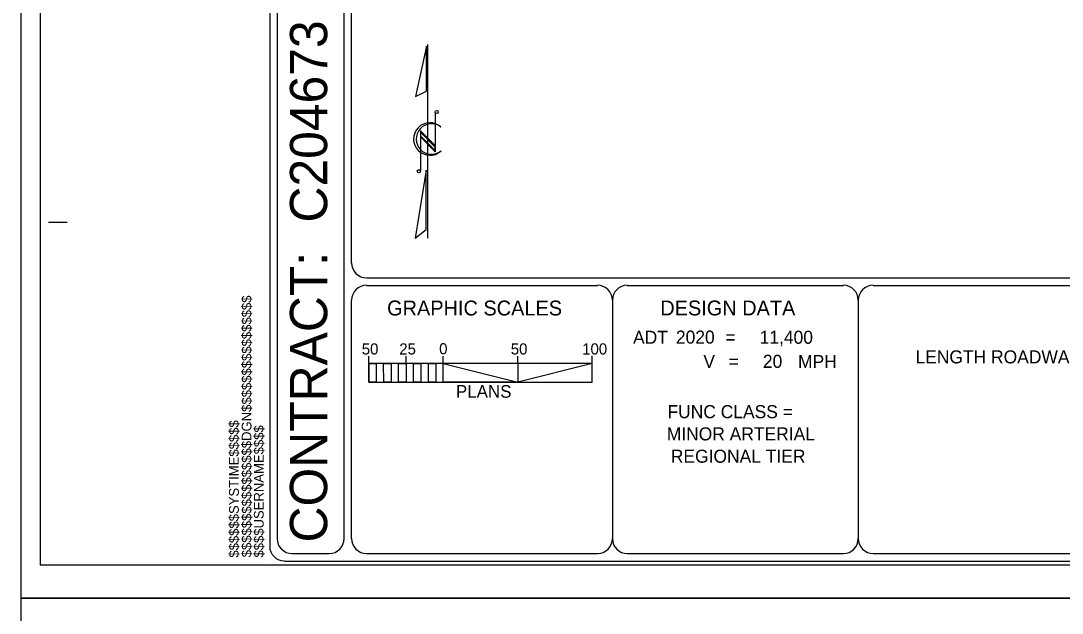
# Model space of a CAD drawing. Extents: x 925297 to 940193, y 663541 to 689899.
# Drawn here: x 925297 to 930888, y 681019 to 684199 of the extents above; entities that cross this region are included whole.
import ezdxf

# ---------------------------------------------------------------- set-up
doc = ezdxf.new("R2010")
doc.units = 0
for name, color, linetype in [('Sheet Cutting Line CELL', 7, 'Continuous'), ('Sheet Data Field CELL', 7, 'Continuous'), ('Sheet North Arrow CELL', 7, 'Continuous'), ('Sheet Plot Border Inside CELL', 7, 'Continuous'), ('Sheet Plot Border Outside CELL', 7, 'Continuous'), ('Sheet Title CELL', 7, 'Continuous')]:
    doc.layers.add(name, color=color, linetype=linetype)

msp = doc.modelspace()

# ---------------------------------------------------------------- linework, layer by layer
at = {"layer": 'Sheet Cutting Line CELL'}
for p, q in [((925296.7, 689898.6), (925296.7, 681098.7)), ((925296.7, 681098.7), (938768.7, 681098.7))]:
    msp.add_line(p, q, dxfattribs=at)
at = {"layer": 'Sheet Data Field CELL'}
for p, q in [((927164.8, 682359.6), (927164.8, 682399.5)), ((927364.8, 682359.5), (927364.8, 682399.5)), ((927964.8, 682359.6), (927964.8, 682399.5)), ((928364.8, 682359.5), (928364.8, 682399.6)), ((926632.8, 681298.7), (926632.8, 681298.7))]:
    msp.add_line(p, q, dxfattribs=at)
at = {"layer": 'Sheet North Arrow CELL'}
for p, q in [((927482.1, 683031.5), (927482.1, 684071.5)), ((927521.3, 683709.6), (927521.3, 683496.1)), ((927521.3, 683529.4), (927441.7, 683608.9)), ((927441.7, 683608.9), (927441.7, 683392)), ((927521.3, 683521.6), (927441.7, 683601.1)), ((927441.7, 683601.1), (927441.7, 683581.6)), ((927550.7, 683630.1), (927551.8, 683629.3)), ((927521.3, 683502.1), (927441.7, 683581.6)), ((927441.7, 683581.6), (927521.3, 683502.1)), ((927521.3, 683496.1), (927441.7, 683575.7)), ((927521.3, 683502.1), (927521.3, 683521.6))]:
    msp.add_line(p, q, dxfattribs=at)
for points in [[(927474.9, 684062.4), (927415.5, 683792.3), (927474.9, 683822.4)], [(927473.6, 683397.9), (927414.7, 683031.5), (927473.6, 683077.9)]]:
    msp.add_lwpolyline(points, close=True, dxfattribs=at)
for centre in [(927529.7, 683709.4), (927433.3, 683391.7)]:
    msp.add_circle(centre, 8.48, dxfattribs=at)
for centre, radius, start, end in [((927493.1, 683564.5), 87.4, 47.84, 312.3941), ((927501.6, 683564.6), 81.9, 53.095, 308.6287)]:
    msp.add_arc(centre, radius, start, end, dxfattribs=at)
at = {"layer": 'Sheet Plot Border Inside CELL'}
msp.add_lwpolyline([(925400.7, 681278.2), (938732.7, 681278.2), (938732.7, 689719), (925400.7, 689719)], close=True, dxfattribs=at)
at = {"layer": 'Sheet Plot Border Outside CELL'}
for points in [[(938768.7, 689898.6), (925296.7, 689898.6), (925296.7, 681098.7), (938768.7, 681098.7)], [(925296.7, 672338.7), (938764.7, 672338.7), (938764.7, 681098.7), (925296.7, 681098.7)]]:
    msp.add_lwpolyline(points, close=True, dxfattribs=at)
at = {"layer": 'Sheet Title CELL'}
for p, q in [((927032.7, 681418.7), (927032.7, 689578.7)), ((927072.7, 682898.7), (927072.7, 689578.7)), ((925444.7, 683118.6), (925544.7, 683118.7)), ((925444.7, 683118.6), (925544.7, 683118.7)), ((927152.7, 682818.7), (938512.7, 682818.7)), ((927152.7, 682778.6), (928392.7, 682778.7)), ((928552.7, 682778.6), (929712.7, 682778.7)), ((929872.7, 682778.6), (932912.7, 682778.6)), ((927072.8, 681418.6), (927072.7, 682698.7)), ((928472.7, 682698.7), (928472.7, 681418.6)), ((929792.7, 682698.7), (929792.7, 681418.7)), ((927164.7, 682359.5), (927164.7, 682399.4)), ((927164.7, 682399.4), (927164.7, 682399.4)), ((927364.7, 682359.4), (927364.7, 682399.5)), ((927564.7, 682359.4), (927564.7, 682399.4)), ((927964.7, 682359.5), (927964.7, 682399.4)), ((928364.7, 682359.5), (928364.7, 682399.5)), ((927164.7, 682359.5), (927164.7, 682259.5)), ((927164.7, 682359.5), (927164.7, 682359.5)), ((928364.7, 682359.5), (927164.7, 682359.5)), ((927444.7, 682359.5), (927444.7, 682259.5)), ((927964.7, 682359.5), (927964.7, 682259.5)), ((928364.7, 682259.4), (928364.7, 682359.5)), ((927164.7, 682259.5), (928364.7, 682259.4)), ((926632.7, 681298.7), (926632.7, 681298.7)), ((926632.7, 681298.7), (926632.7, 681298.7)), ((926632.7, 681298.7), (926632.7, 681298.7)), ((926632.7, 681298.7), (926632.7, 681298.7))]:
    msp.add_line(p, q, dxfattribs=at)
for points in [[(926632.7, 689618.7), (926632.7, 681378.7)], [(926632.7, 689618.7), (926632.7, 681378.7)], [(926672.8, 689578.7), (926672.7, 681418.7)], [(926752.6, 681338.7), (926952.7, 681338.7)], [(927152.7, 681338.6), (928392.7, 681338.7)], [(928552.7, 681338.7), (929712.7, 681338.7)], [(929872.7, 681338.6), (932912.7, 681338.6)], [(926712.7, 681298.6), (938552.7, 681298.6)]]:
    msp.add_lwpolyline(points, dxfattribs=at)
for points in [[(927164.7, 682359.5), (927204.7, 682359.5), (927204.7, 682259.5), (927164.7, 682259.5)], [(927244.7, 682359.5), (927284.7, 682359.4), (927284.7, 682259.4), (927244.8, 682259.4)], [(927324.7, 682359.4), (927364.7, 682359.4), (927364.7, 682259.5), (927324.7, 682259.5)], [(927404.7, 682359.4), (927444.7, 682359.5), (927444.7, 682259.5), (927404.7, 682259.5)], [(927484.7, 682359.5), (927524.7, 682359.5), (927524.7, 682259.4), (927484.7, 682259.5)], [(927564.7, 682359.4), (927964.7, 682259.5), (927564.7, 682259.4)], [(928364.7, 682359.5), (927964.7, 682259.5), (928364.7, 682259.4)]]:
    msp.add_lwpolyline(points, close=True, dxfattribs=at)
for centre, start, end in [((927152.7, 682899.1), 180, 270), ((927152.7, 682699.1), 90, 180), ((928392.7, 682699.1), 0, 90), ((928552.7, 682699.1), 90, 180), ((929712.7, 682699.1), 0, 90), ((929872.7, 682699.1), 90, 180), ((926712.7, 681379.1), 180, 270), ((926752.7, 681419.1), 180, 270), ((926952.7, 681419.1), 270, 360), ((927152.7, 681419.1), 180, 270), ((928392.7, 681419.1), 270, 360), ((928552.7, 681419.1), 180, 270), ((929712.7, 681419.1), 270, 360), ((929872.7, 681419.1), 180, 270)]:
    msp.add_arc(centre, 80, start, end, dxfattribs=at)

# ---------------------------------------------------------------- texts
at = {"layer": 'Sheet Data Field CELL'}
for s, p in [('ADT', (928583.8, 682465.2)), ('=', (929079.4, 682465.6)), ('V', (928961.3, 682335.2)), ('=', (929096.8, 682336)), ('20', (929280.8, 682335.9)), ('MPH', (929469.6, 682334.8)), ('FUNC CLASS =', (928768.4, 682065.7))]:
    msp.add_text(s, height=70, rotation=360, dxfattribs=at).set_placement(p)
for s, height, p in [('2020', 70, (928813.8, 682466.1)), ('11,400', 70, (929263.3, 682465.3)), ('50', 60, (927127.3, 682407.5)), ('25', 60, (927328.5, 682407.5)), ('50', 60, (927927.3, 682407.5)), ('100', 60, (928310.8, 682407.6)), ('LENGTH ROADWAY TIP PROJECT HL-0003 = 2.0 MILES', 70.001, (930100, 682359.8)), ('MINOR ARTERIAL', 70, (928764.6, 681946.5)), ('REGIONAL TIER', 70, (928786.5, 681826.5))]:
    msp.add_text(s, height=height, dxfattribs=at).set_placement(p)
at = {"layer": 'Sheet Title CELL'}
for s, height, rotation, p in [('C204673', 200, 90, (926941.6, 683116.2)), ('CONTRACT:', 200, 90, (926941.6, 681398.4)), ('$$$$$$$$$$$$$$$$DGN$$$$$$$$$$$$$$$$', 52.5, 90, (926535, 681318.8)), ('GRAPHIC SCALES', 79.997, 360, (927263.2, 682617.1)), ('DESIGN DATA', 79.997, 360, (928729.9, 682617.4)), ('0', 60, 360, (927542.7, 682408.6)), ('PLANS', 68, 360, (927632.7, 682175.4)), ('$$$$$$SYSTIME$$$$$', 52.5, 90, (926467, 681316.8)), ('$$$$USERNAME$$$$', 52.5, 90, (926600.6, 681317.4))]:
    msp.add_text(s, height=height, rotation=rotation, dxfattribs=at).set_placement(p)

doc.saveas('drawing.dxf')
